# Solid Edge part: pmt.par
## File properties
Title: PMT
Subject: SHMS Cerenkov
Author: Owner
Template: Iso Part.par
Last saved by: Lee
Revision: 26
Application: Solid Edge
Material: Multiple
Face Style: Model Default
Fill Style: Default
Coef. of Thermal Exp: 0.0
Thermal Conductivity: 0.0
Specific Heat: 0.0
Modulus of Elasticity: 0.0
Poisson's Ratio: 0.0
Yield Stress: 0.0
Ultimate Stress: 0.0
Elongation: 0.0
Manager: Garth Huber
Company: U of R Physics
Accuracy: 0.990
Document Number: 1
Project Name: SHMS Cerenkov
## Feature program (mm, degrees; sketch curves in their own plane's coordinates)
sketch for "unnamed RevolvedProtrusion 1" plane through (0, 0, 0) normal (0, -1, 0) x-axis (1, 0, 0)
  line (0, 0) -> (0, 360)
  line (0, 360) -> (37, 360)
  line (37, 360) -> (37, 259)
  line (37, 259) -> (38.5, 259)
  line (38.5, 196) -> (38.5, 259)
  line (38.5, 196) -> (71, 140)
  line (71, 0) -> (71, 140)
  line (0, 0) -> (71, 0)
revolve "unnamed RevolvedProtrusion 1" add full turn 360 deg
sketch for "unnamed RevolvedCutout 1" plane through (0, 0, 0) normal (1, 0, 0) x-axis (0, 1, 0)
  line (66.5, 0) -> (66.5, 18.46)
  line (66.5, 18.46) -> (63.84, 18.46)
  arc centre (0.0081, 134) radius 132 from (63.84, 18.46) to (0, 2) cw
  line (0, 2) -> (0, 0)
  line (0, 0) -> (66.5, 0)
revolve "unnamed RevolvedCutout 1" cut full turn 360 deg
sketch for "unnamed Protrusion 1" plane through (0, 0, 360) normal (0, 0, 1) x-axis (0, 1, 0)
  circle centre (20, 0) radius 6
extrude "unnamed Protrusion 1" add finite 15 along +normal
sketch for "ExtrudedProtrusion_2" plane through (0, 0, 360) normal (0, 0, 1) x-axis (0, 1, 0)
  circle centre (-20, 0) radius 5
extrude "ExtrudedProtrusion_2" add finite 10 along +normal
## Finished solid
Body 1: solid body, 14 faces, 13 edges, 1 vertex.
  Faces by surface: cylinder 6, plane 6, cone 1, torus 1
  Edges by curve: circle 13
Bounding box of the edges (mm; curved faces can reach further): 142.000 x 142.000 x 375.000, from (-71, -71, 0) to (71, 71, 375).
Cylindrical faces by radius (mm): R5 x1, R6 x1, R37 x1, R38.5 x1, R66.5 x1, R71 x1
Conical faces (half-angle, radius in mm at the cone's reference point): 30.129 deg R38.5 x1
Toroidal faces (ring radius, tube radius in mm): R0.0081 r132 x1
Planar faces by outward normal: +z 4, -z 2
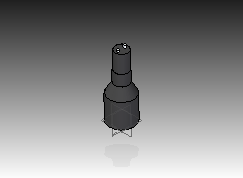
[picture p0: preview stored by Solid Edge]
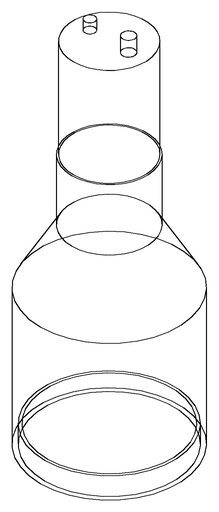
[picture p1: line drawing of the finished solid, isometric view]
